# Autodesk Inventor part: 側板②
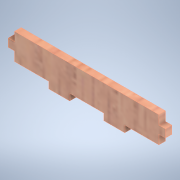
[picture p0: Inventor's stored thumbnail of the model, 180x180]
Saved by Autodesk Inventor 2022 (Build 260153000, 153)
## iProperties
Created: 2024-11
Part Number: 側板②
Material: 木 (オーク)
Document SubType Name: Modeling
Designer: shimizu
Density: 0.76 g/cm^3
Appearance: ホワイト オーク材 - ナチュラル 標準の光沢
Author: shimizu
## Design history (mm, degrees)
sketch "スケッチ1"
  geometry: L1 (-25.358, 1.343)-(29.642, 1.343); L2 (-4.358, -8.657)-(-4.358, -11.157); L3 (-4.358, -11.157)-(-12.358, -11.157); L4 (-12.358, -11.157)-(-12.358, -8.657); L5 (16.642, -8.657)-(16.642, -11.157); L6 (16.642, -11.157)-(8.642, -11.157); L7 (8.642, -11.157)-(8.642, -8.657); L8 (-25.358, -2.157)-(-27.858, -2.157); L9 (-27.858, -2.157)-(-27.858, -5.157); L10 (-27.858, -5.157)-(-25.358, -5.157); L11 (29.642, -2.157)-(32.142, -2.157); L12 (32.142, -2.157)-(32.142, -5.157); L13 (32.142, -5.157)-(29.642, -5.157); L14 (-25.358, -8.657)-(-25.358, -5.157); L15 (-25.358, -2.157)-(-25.358, 1.343); L16 (29.642, 1.343)-(29.642, -2.157); L17 (29.642, -5.157)-(29.642, -8.657); L18 (29.642, -8.657)-(16.642, -8.657); L19 (8.642, -8.657)-(-4.358, -8.657); L20 (-12.358, -8.657)-(-25.358, -8.657); 1 further point
  constraints: 40 end point, 11 parallel, 4 perpendicular, 3 horizontal
  dimensions: "d16" = 13 distance of L17.end L5.start; "d17" = 13 distance of L4.end L14.start; "d18" = 8 distance of L5.end L6.end; "d19" = 8 distance of L2.end L3.end; "d20" = 13 distance of L7.end L2.start; "d21" = 55 distance between parallel lines of L16 L15; "d22" = 60 distance between parallel lines of L12 L9
extrude "押し出し1" new body sketch "スケッチ1" distance "d14" = 2.5; taper "d15" = 0 deg
node "ソリッド1"
